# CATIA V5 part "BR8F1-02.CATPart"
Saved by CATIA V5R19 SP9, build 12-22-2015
Part number: BR8F1-02
Definition: design
Nomenclature: BR8F1-02
Source: Unknown
Bounding box of the stored display mesh (mm): x -3.9 to 11.15, y 0 to 18.1, z 0 to 10.16
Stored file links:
  Z:\charly_robot\BR8F1-02.CATPart
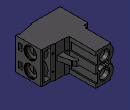
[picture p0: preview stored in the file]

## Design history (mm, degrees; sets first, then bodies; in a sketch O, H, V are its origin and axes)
AxisSystem1: origin (0, 0, 0), X (1, 0, 0), Y (0, 1, 0), Z (0, 0, 1)
Body1 "MANIFOLD_SOLID_BREP #36744" (main body)
  Solid1: solid without history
